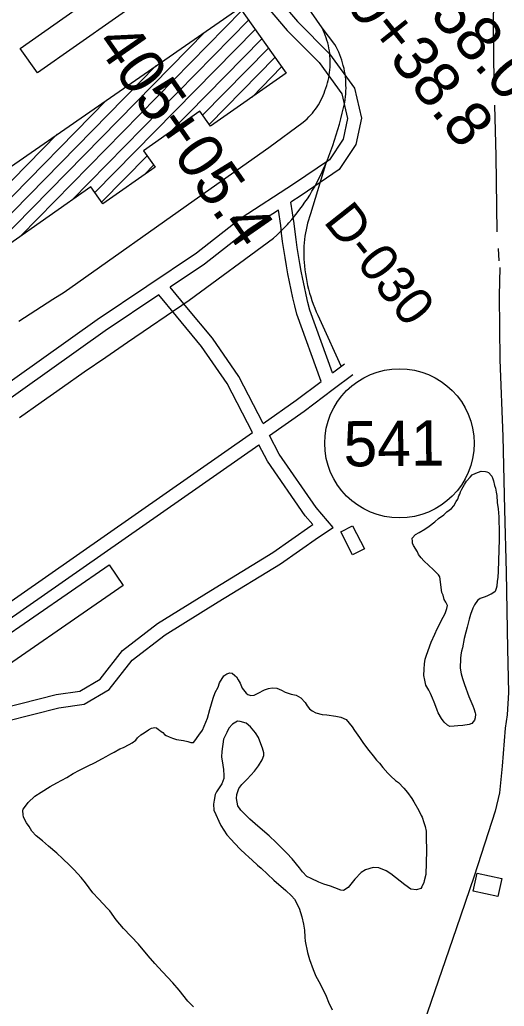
# Model space of a CAD drawing. Extents: x 3625074 to 3663148, y 511451 to 537151.
# Drawn here: x 3645512 to 3646582, y 518337 to 520518 of the extents above; entities that cross this region are included whole.
import ezdxf

# ---------------------------------------------------------------- set-up
doc = ezdxf.new("R2010")
doc.units = 0
for name, color, linetype in [('V-BLDG-OTLN', 7, 'Continuous'), ('V-RAIL-TRAK', 7, 'Continuous'), ('V-RIVR-RANG-IDEN', 7, 'Continuous'), ('V-ROAD-CNTR', 7, 'Continuous'), ('V-ROAD-IDEN', 7, 'Continuous'), ('V-SITE-VEGE', 7, 'Continuous'), ('V-SURV-IDEN', 7, 'Continuous'), ('V-TOPO-SHOR', 7, 'Continuous')]:
    doc.layers.add(name, color=color, linetype=linetype)

msp = doc.modelspace()

# ---------------------------------------------------------------- linework, layer by layer
at = {"layer": 'V-BLDG-OTLN'}
for p, q in [((3645513.8, 520040), (3646002.1, 520538.2)), ((3645626.7, 520119.5), (3646016.7, 520517.4)), ((3645400.9, 519960.6), (3645921.3, 520491.5)), ((3645677.7, 520135.8), (3646031.4, 520496.7)), ((3645843.4, 520269.1), (3646046.1, 520475.9)), ((3645915.5, 520307), (3646060.8, 520455.2)), ((3645091.6, 519680.7), (3645812.2, 520415.9)), ((3645930.1, 520286.2), (3646075.4, 520434.5)), ((3646024.8, 520347.1), (3646090.1, 520413.7)), ((3645077, 519701.5), (3645703.1, 520340.3)), ((3645033.4, 519692.7), (3645594.1, 520264.7)), ((3645692.4, 520115), (3645792.8, 520217.5)), ((3645787.2, 520176.1), (3645807.4, 520196.7))]:
    msp.add_line(p, q, dxfattribs=at)
for points in [[(3645512.3, 520454.8), (3645857.3, 520697.7), (3645895.5, 520643.3), (3645550.5, 520400.5)], [(3643978.6, 519134.6), (3644983.5, 519841.7), (3645997.7, 520544.4), (3646099.9, 520399.9), (3645932.9, 520282.4), (3645909.4, 520315.6), (3645785.3, 520228.2), (3645810.4, 520192.4), (3645695, 520111.2), (3645668.5, 520148.9), (3645299.4, 519889.1), (3645306.3, 519879.2), (3645243.5, 519834.9), (3645274.7, 519790.6), (3645100.6, 519668.1), (3645066.7, 519716.2), (3644966.6, 519645.7), (3645085.1, 519477.3), (3644183.9, 518842.9)], [(3646246.6, 519399.4), (3646272.9, 519348.2), (3646247, 519334.9), (3646220.7, 519386.1)], [(3645740.3, 519267.2), (3645407.2, 519037.4), (3645375.8, 519082.9), (3645708.9, 519312.7)], [(3646513.1, 518591.9), (3646522.2, 518631.7), (3646576.7, 518619.3), (3646567.6, 518579.5)]]:
    msp.add_lwpolyline(points, close=True, dxfattribs=at)
at = {"layer": 'V-RAIL-TRAK'}
for points in [[(3645610.1, 519915.8), (3645909.1, 520128.2), (3646061.7, 520235.3), (3646137.6, 520291.6), (3646142, 520295.3), (3646146.2, 520299.1), (3646150.3, 520303.2), (3646154.2, 520307.3), (3646158, 520311.6), (3646161.6, 520316), (3646165, 520320.6), (3646168.3, 520325.3), (3646171.4, 520330.1), (3646174.3, 520335.1), (3646177, 520340.1), (3646179.5, 520345.2), (3646181.8, 520350.5), (3646184, 520355.8), (3646185.9, 520361.2), (3646187.9, 520366.8), (3646189.8, 520372.5), (3646191.4, 520378.2), (3646192.9, 520384), (3646194.2, 520389.8), (3646195.2, 520395.7), (3646196.1, 520401.6), (3646196.7, 520407.6), (3646197.2, 520413.5), (3646197.4, 520419.5), (3646197.4, 520425.5), (3646197.3, 520431.4), (3646196.9, 520437.4), (3646196.3, 520443.4), (3646195.5, 520449.3), (3646194.5, 520455.2), (3646193.3, 520461), (3646191.9, 520466.8), (3646190.3, 520472.6), (3646188.5, 520478.3), (3646186.6, 520483.9), (3646184.4, 520489.5), (3646182, 520495), (3646179.5, 520500.4), (3646109.2, 520602.8)], [(3645749.6, 519805.2), (3645885.5, 519898), (3646072.3, 520035), (3646079.4, 520041.5), (3646086.3, 520048.2), (3646093, 520055), (3646099.7, 520062), (3646102.9, 520065.5), (3646106.1, 520069.1), (3646112.5, 520076.4), (3646118.6, 520083.7), (3646124.6, 520091.2), (3646130.5, 520098.9), (3646136.2, 520106.6), (3646141.7, 520114.5), (3646147, 520122.4), (3646152.2, 520130.5), (3646157.2, 520138.7), (3646162.6, 520148.1), (3646167.7, 520157.6), (3646172.6, 520167.2), (3646177.4, 520176.8), (3646181.9, 520186.6), (3646186.2, 520196.5), (3646190.4, 520206.4), (3646194.3, 520216.5), (3646198.7, 520228.1), (3646202.9, 520239.8), (3646206.9, 520251.5), (3646210.8, 520263.3), (3646214.4, 520275.2), (3646217.8, 520287.1), (3646221, 520299.1), (3646224, 520311.2), (3646226.8, 520323.3), (3646229.4, 520335.4), (3646230.4, 520341.7), (3646231.2, 520347.9), (3646231.8, 520354.2), (3646232.2, 520360.5), (3646232.4, 520366.8), (3646232.3, 520373.1), (3646232.1, 520379.4), (3646231.7, 520385.7), (3646231, 520391.9), (3646230.2, 520398.2), (3646229.1, 520404.4), (3646227.9, 520410.6), (3646226.4, 520416.7), (3646224.8, 520422.8), (3646222.9, 520428.8), (3646220.9, 520434.8), (3646218.6, 520440.7), (3646216.2, 520446.5), (3646213.6, 520452.2), (3646210.8, 520457.9), (3646207.8, 520463.4), (3646179.5, 520500.4)], [(3646187, 520198.3), (3646153.8, 520089.1), (3646151.5, 520082.2), (3646149.3, 520075.2), (3646147.4, 520068.2), (3646145.6, 520061.1), (3646144.1, 520053.9), (3646142.7, 520046.7), (3646141.6, 520039.5), (3646140.6, 520032.3), (3646139.9, 520025), (3646139.4, 520017.7), (3646139, 520010.5), (3646138.9, 520003.1), (3646139, 519995.8), (3646139.3, 519988.6), (3646139.8, 519981.3), (3646140.4, 519974), (3646141.4, 519965.3), (3646142.6, 519956.6), (3646144, 519948), (3646145.6, 519939.4), (3646147.5, 519930.8), (3646149.5, 519922.3), (3646151.8, 519913.8), (3646154.3, 519905.5), (3646157, 519897.1), (3646159.9, 519888.9), (3646163.1, 519880.7), (3646166.4, 519872.6), (3646170, 519864.6), (3646173.7, 519856.7), (3646177.7, 519848.9), (3646221, 519753)], [(3645509.6, 519851.6), (3645534.6, 519867.9), (3645559.7, 519884), (3645584.9, 519900), (3645610.1, 519915.8)], [(3645511.4, 519639), (3645558.8, 519672.6), (3645606.3, 519706), (3645654, 519739.3), (3645701.7, 519772.3), (3645749.6, 519805.2)]]:
    msp.add_lwpolyline(points, dxfattribs=at)
at = {"layer": 'V-ROAD-CNTR'}
for points in [[(3645874, 520975.9), (3645873.3, 520923), (3645868.2, 520874.8), (3645872.4, 520828.5), (3645909.6, 520766.6), (3646007.1, 520652.7), (3646124.9, 520514.2), (3646195.5, 520442.7), (3646251.3, 520366.7), (3646266.2, 520300.3), (3646254.2, 520242), (3646217.2, 520186.7), (3646133.3, 520129.5), (3646110.5, 520114.8)], [(3645842.4, 520826.9), (3645843.1, 520818.9), (3645885.2, 520748.9), (3645984.3, 520633.2), (3646102.7, 520493.9), (3646172.7, 520423.2), (3646223.4, 520354), (3646235.5, 520300), (3646226, 520253.8), (3646195.5, 520208.2), (3646116.7, 520154.5), (3646000.6, 520079.5), (3645902.1, 520001.7), (3645682.9, 519854.8), (3645377.4, 519637.4), (3644972.2, 519346.6), (3644537.2, 519051), (3644252.9, 518839.5), (3644101.4, 518739.4)], [(3646202.5, 519737.4), (3646152.5, 519876.1), (3646148.3, 519892.6), (3646144.3, 519909.9), (3646140.4, 519927.2), (3646136.8, 519944.5), (3646133.4, 519961.9), (3646130.2, 519979.4), (3646127.3, 519996.9), (3646124.6, 520014.4), (3646122.1, 520032), (3646119.8, 520049.5), (3646117.7, 520067.5), (3646110.5, 520114.8)], [(3646082.9, 520096.9), (3646018.1, 520055.1), (3645919.8, 519977.5), (3645844, 519926.7)], [(3646177.4, 519718.6), (3646123.7, 519867.3), (3646119.2, 519885.5), (3646115, 519903.2), (3646111.1, 519920.9), (3646107.4, 519938.6), (3646103.9, 519956.4), (3646100.7, 519974.2), (3646097.7, 519992.1), (3646094.9, 520010), (3646092.3, 520027.9), (3646090, 520045.9), (3646088, 520063.5), (3646082.9, 520096.9)], [(3646049.4, 519625.6), (3645995.5, 519729.5), (3645937.2, 519813.8), (3645880.7, 519882), (3645844, 519926.7)], [(3645819, 519909.9), (3645700, 519830.1), (3645394.9, 519613), (3644989.4, 519322), (3644554.6, 519026.5), (3644270.2, 518815), (3644116.1, 518713.2)], [(3646026.1, 519605.5), (3645969.8, 519714), (3645913.3, 519795.6), (3645857.6, 519862.9), (3645819, 519909.9)], [(3646202.5, 519737.4), (3646229.3, 519757.5)], [(3646049.4, 519625.6), (3646122.1, 519677.2), (3646177.4, 519718.6)], [(3646063.4, 519598.7), (3646139.8, 519652.9), (3646204.2, 519701.2), (3646247.3, 519733.5)], [(3644116.1, 518713.2), (3644124.9, 518697.5), (3644181.8, 518583.5), (3644266.4, 518486.3), (3644335, 518407.2), (3644330, 518410.6), (3644530.1, 518556.3), (3644967.6, 518852.4), (3645377, 519152.7), (3646026.1, 519605.5)], [(3645192.9, 518980.5), (3645266.9, 518915.3), (3645319.7, 518914.4), (3645481.8, 518967.2), (3645598.3, 518996.7), (3645654.2, 519005.1), (3645709.2, 519037.6), (3645760.2, 519102), (3645832.8, 519158.5), (3645949.7, 519230.9), (3646087.3, 519315.4), (3646171.3, 519374.4), (3646204, 519395.6), (3646166.1, 519440), (3646084.6, 519557.7), (3646063.4, 519598.7)], [(3645217.7, 518998.6), (3645394.4, 519128.3), (3646040, 519578.6)], [(3645217.7, 518998.6), (3645278.4, 518945.1), (3645315.2, 518944.4), (3645473.5, 518996.1), (3645592.4, 519026.2), (3645644, 519033.9), (3645689.2, 519060.6), (3645738.9, 519123.5), (3645815.6, 519183.1), (3645933.9, 519256.5), (3646070.8, 519340.5), (3646154.5, 519399.3), (3646158.9, 519402.2), (3646142.3, 519421.6), (3646058.9, 519542.2), (3646040, 519578.6)]]:
    msp.add_lwpolyline(points, dxfattribs=at)
at = {"layer": 'V-ROAD-IDEN'}
msp.add_circle((3646350.4, 519581.6), 165, dxfattribs=at)
msp.add_circle((3646350.4, 519581.6), 165, dxfattribs=at)
at = {"layer": 'V-SITE-VEGE'}
for points in [[(3646419.1, 519028.6), (3646415.2, 519035.7), (3646408.6, 519047), (3646406.5, 519058.2), (3646404.5, 519068.2), (3646404.9, 519082.2), (3646405.8, 519094.4), (3646407.3, 519104.3), (3646409.9, 519113.5), (3646420.6, 519141.8), (3646428.7, 519159.7), (3646433.7, 519171.8), (3646446.7, 519197.1), (3646451, 519205.2), (3646454.8, 519216.7), (3646456.2, 519223.1), (3646452.9, 519230.2), (3646449.5, 519236.2), (3646446.9, 519246.2), (3646445.2, 519249.1), (3646444.1, 519252.1), (3646439.3, 519286.6), (3646436.5, 519290.8), (3646425.2, 519302.8), (3646415.5, 519311.3), (3646404.1, 519322.1), (3646398.4, 519328.1), (3646392.8, 519335.8), (3646390.1, 519341.7), (3646381.1, 519356), (3646379.5, 519360.7), (3646379, 519364.8), (3646378.7, 519371.8), (3646385.9, 519379.8), (3646393.6, 519384.3), (3646406.7, 519392.1), (3646416.2, 519398.8), (3646428.7, 519408.4), (3646436.5, 519415.7), (3646448.4, 519423.6), (3646455, 519429.8), (3646465.2, 519437.7), (3646470.6, 519443.4), (3646475.5, 519453.1), (3646479.2, 519458.3), (3646481.7, 519465.2), (3646483.6, 519469.3), (3646485.5, 519474.5), (3646488, 519480.2), (3646494.1, 519490.6), (3646498.4, 519498), (3646506.8, 519506.5), (3646511.1, 519511.7), (3646519.3, 519515.5), (3646531.1, 519519.9), (3646540.5, 519519.6), (3646543.4, 519518.9), (3646546.8, 519517.1), (3646554.7, 519508.7), (3646556.9, 519502.8), (3646558.5, 519498.7), (3646560.6, 519488.7), (3646562.2, 519482.8), (3646563.7, 519474), (3646565.2, 519466.4), (3646566.5, 519450.6), (3646568.5, 519437.1), (3646569.7, 519419), (3646570, 519408.4), (3646570.7, 519393.2), (3646570.4, 519380.4), (3646570.6, 519369.3), (3646568.6, 519299.3), (3646567.7, 519285.3), (3646566.3, 519276.6), (3646565.4, 519265.6), (3646564.1, 519260.9), (3646561.5, 519254), (3646559.1, 519251.7), (3646553.2, 519247.8), (3646550.8, 519247.3), (3646543.1, 519244), (3646537.2, 519241.8), (3646529, 519238.6), (3646523, 519234.1), (3646516.3, 519224.3), (3646512.6, 519216.9), (3646507.5, 519203), (3646504.3, 519192.6), (3646499.7, 519175.2), (3646497.1, 519164.2), (3646493.2, 519150.3), (3646489.7, 519129.4), (3646487.7, 519121.8), (3646485.7, 519113.7), (3646484.9, 519105.6), (3646484.3, 519084.6), (3646486.9, 519071.7), (3646489.5, 519061.7), (3646493.8, 519048.7), (3646503.6, 519021.6)], [(3645530.3, 518787.7), (3645545.3, 518801.3), (3645558.9, 518810.2), (3645579.1, 518823.1), (3645593.4, 518830.8), (3645615.3, 518843.1), (3645629.6, 518852), (3645643.8, 518859.2), (3645662.7, 518868.6), (3645676.4, 518875.2), (3645694.1, 518884.6), (3645702.5, 518889.6), (3645713.1, 518895.2), (3645720.2, 518899), (3645732.7, 518906.3), (3645740.9, 518909), (3645753.4, 518915.6), (3645759.9, 518919.5), (3645767.7, 518925.7), (3645771.9, 518930.3), (3645779.1, 518937.1), (3645786.2, 518941.5), (3645795.8, 518948.3), (3645802.3, 518952.2), (3645809.9, 518953.1), (3645814, 518952.4), (3645818, 518948.8), (3645820.3, 518947.6), (3645824.3, 518944.5), (3645827.7, 518942.1), (3645831.7, 518937.9), (3645835.1, 518935.5), (3645841.4, 518932.4), (3645848.9, 518929.8), (3645857.6, 518927.2), (3645873.3, 518924.5), (3645883.2, 518922.4), (3645889.5, 518920.5), (3645895.4, 518920.3), (3645898.4, 518923.8), (3645907.5, 518936.3), (3645915.4, 518947.8), (3645926.1, 518973.8), (3645931.3, 518993.5), (3645939, 519018.3), (3645943.4, 519030.5), (3645949.6, 519042.5), (3645952.8, 519052.4), (3645962.6, 519067.3), (3645969.1, 519071.8), (3645975.6, 519073.9), (3645980.8, 519073.2), (3645987.1, 519068.3), (3645990.5, 519065.3), (3645994.4, 519058.8), (3645998.3, 519051.1), (3646003.3, 519040.4), (3646011.7, 519029.1), (3646015.7, 519026.1), (3646022.1, 519024.1), (3646029.1, 519024.5), (3646038, 519029.5), (3646052.2, 519036.7), (3646061, 519039.4), (3646069.2, 519040.9), (3646079.7, 519040), (3646089.5, 519035.7), (3646097.6, 519031.3), (3646111.5, 519027.4), (3646122.5, 519024.8), (3646132.2, 519019.3), (3646142.4, 519008.5), (3646146.3, 519001.4), (3646152, 518994.8), (3646157.7, 518990.5), (3646165.7, 518985.6), (3646179.6, 518982.3), (3646190.1, 518981.4), (3646209.9, 518978.5)], [(3646503.6, 519021.6), (3646512.3, 519001.5), (3646514.5, 518995.6), (3646517.7, 518985.6), (3646518.2, 518983.2), (3646518, 518975), (3646516.1, 518969.3), (3646510.6, 518962.4), (3646504.7, 518960.2), (3646490.7, 518957.7), (3646479, 518956.9), (3646471.4, 518956.5), (3646461.4, 518955.6), (3646456.8, 518958.7), (3646448.8, 518965.3), (3646443.2, 518973.1), (3646436, 518985.5), (3646433.8, 518992), (3646430.6, 518999.7), (3646426.8, 519009.7), (3646423.5, 519018), (3646419.1, 519028.6)], [(3646209.9, 518978.5), (3646220.9, 518976.5), (3646232.4, 518970.9), (3646246, 518954.7), (3646251, 518946.4), (3646262.3, 518931.5), (3646269.5, 518920.2), (3646277.4, 518909.5), (3646283, 518902.9), (3646292.6, 518890.4), (3646299.9, 518881.4), (3646306.2, 518874.2), (3646313.5, 518864.7), (3646324.8, 518852.1), (3646331, 518846.1), (3646341.3, 518835.9), (3646348.1, 518831.6), (3646360, 518819), (3646368, 518809.4), (3646377.5, 518796.3), (3646382, 518789.2), (3646393.1, 518770.2), (3646398.6, 518759), (3646400.8, 518754.8), (3646404.6, 518743.6), (3646407.3, 518734.2), (3646409.3, 518724.2), (3646409.1, 518718.4), (3646409.4, 518708.4), (3646409.3, 518702), (3646410.1, 518689.7), (3646410.4, 518681), (3646408.9, 518628.5), (3646405, 518614.6), (3646404.3, 518610.5), (3646400, 518601.3), (3646397.5, 518597.3), (3646388.1, 518594.6), (3646375.3, 518596.2), (3646362.2, 518605.9), (3646331.3, 518630.1), (3646321, 518636.8), (3646304.9, 518643.1), (3646292, 518644.1), (3646275.5, 518638.7), (3646265.5, 518633.1), (3646251.6, 518617.8), (3646237.1, 518599.5), (3646227, 518593.4), (3646220.6, 518593.6), (3646207.3, 518598.6), (3646198, 518602.4), (3646183, 518606.9), (3646172.6, 518611.3), (3646155.3, 518619.3), (3646146.1, 518624.3), (3646135.9, 518634.5), (3646129.7, 518642.8), (3646113.4, 518663.1), (3646101.5, 518675.7), (3646095.8, 518681.2), (3646078.2, 518699.2), (3646062.9, 518713.6), (3646037.2, 518735.4), (3646020.1, 518751), (3645999.7, 518770.3), (3645993, 518780.4), (3645990.5, 518796.2), (3645990.8, 518805.6), (3645995.8, 518818.3), (3646001.9, 518827.4), (3646013.9, 518839.3), (3646030.2, 518857), (3646039.2, 518868.4), (3646047.2, 518882.2), (3646051, 518891.4), (3646051.1, 518897.2), (3646047.9, 518907.8), (3646044.1, 518917.3), (3646038.7, 518931.4), (3646032.6, 518941.5), (3646021.3, 518954.7), (3646011.6, 518962.6), (3645998.3, 518967), (3645992.4, 518967.2), (3645985.3, 518963.3), (3645981.7, 518961.1), (3645973.3, 518952), (3645969, 518942.2), (3645961.5, 518927.8), (3645957.8, 518900.5), (3645957.5, 518888.8), (3645959.9, 518870.1), (3645961.4, 518860.7), (3645962.8, 518847.2), (3645962.6, 518840.8), (3645960.6, 518834.4), (3645958.2, 518829.2), (3645953.9, 518822.4), (3645946, 518810.9), (3645943.5, 518805.1)], [(3645943.5, 518805.1), (3645940.8, 518793), (3645939.4, 518783.7), (3645940.7, 518770.8), (3645944.5, 518760.8), (3645951.1, 518746.6), (3645955.5, 518736.5), (3645969, 518716.3), (3645978.6, 518706.1), (3645985.9, 518697.7), (3645999.6, 518683.9), (3646009.2, 518674.3), (3646017.8, 518667), (3646025.1, 518659.8), (3646036.5, 518649), (3646045.1, 518642.3), (3646072.9, 518615.8), (3646099.1, 518592.9), (3646112.2, 518580.9), (3646118.4, 518573.7), (3646129, 518554.1), (3646134.8, 518534.7), (3646138.5, 518518.8), (3646140.4, 518505.4), (3646141.2, 518490.2), (3646142.1, 518480.8), (3646147.2, 518456.1), (3646152, 518440.8), (3646159.6, 518418.4), (3646165.6, 518403.7), (3646175, 518386.5), (3646188.2, 518359.8), (3646193.7, 518346.2), (3646201.4, 518329.1)], [(3645895.1, 518335.5), (3645883.2, 518348.6), (3645864.1, 518372.5), (3645849.9, 518388.7), (3645827.3, 518413.3), (3645809.7, 518431.9), (3645795, 518448.6), (3645773.6, 518474.3), (3645740.7, 518509.1), (3645724.3, 518528.3), (3645710.3, 518547.9), (3645709.4, 518549.8), (3645705.2, 518553.3), (3645685.3, 518574.9), (3645672.9, 518588.1), (3645657.2, 518610.1), (3645647, 518622.1), (3645631.7, 518638.9), (3645622.1, 518648.5), (3645606.1, 518663.5), (3645593.6, 518675.6), (3645575.4, 518690.7), (3645561.7, 518702.7), (3645548, 518714.2), (3645538.4, 518724.4), (3645532.3, 518734.5), (3645526.7, 518742.8), (3645520, 518755.3), (3645519, 518761.2), (3645518.1, 518768.8), (3645519.4, 518772.8), (3645524.2, 518779.7), (3645530.3, 518787.7)]]:
    msp.add_lwpolyline(points, dxfattribs=at)
at = {"layer": 'V-TOPO-SHOR'}
msp.add_line((3646568.4, 520012.2), (3646569.6, 519985), dxfattribs=at)
for points in [[(3646315.1, 521182.8), (3646354, 521144.6), (3646375, 521120.8), (3646406.9, 521080.2), (3646438, 521033.4), (3646467.6, 520982.3), (3646491.7, 520934), (3646513.5, 520873.6), (3646533.6, 520812), (3646542.9, 520772.6), (3646549.1, 520732.8), (3646553.3, 520680.6), (3646559.1, 520621.4), (3646557.4, 520503.7), (3646559.2, 520379)], [(3646560.6, 520329.1), (3646563.6, 520216.5), (3646565.4, 520048.9)], [(3646572.4, 519970), (3646571, 519907.9), (3646572.1, 519766.1), (3646578.9, 519596.4), (3646582.3, 519435.5), (3646586.1, 519296.8), (3646588.7, 519127.4), (3646591.2, 519030.6), (3646588, 518981.4), (3646583.8, 518952.2), (3646577.2, 518868.2), (3646571.1, 518809.1), (3646561.9, 518768.5), (3646515.2, 518624.9), (3646475.5, 518508)], [(3646475.5, 518508), (3646412.3, 518323.9), (3646365, 518184.8)]]:
    msp.add_lwpolyline(points, dxfattribs=at)

# ---------------------------------------------------------------- texts
at = {"layer": 'V-RIVR-RANG-IDEN'}
msp.add_text('D-030', height=83, rotation=308.4343, dxfattribs=at).set_placement((3646180.8, 520071.5))
at = {"layer": 'V-ROAD-IDEN'}
msp.add_text('541', height=100, rotation=0.575, dxfattribs=at).set_placement((3646227.3, 519530.4))
at = {"layer": 'V-SURV-IDEN'}
for s, rotation, p in [('411+70.8', 312.242, (3646346.1, 520812.6)), ('410+58.0', 311.2412, (3646216.2, 520754.1)), ('409+38.8', 308.5875, (3646137.4, 520667.1)), ('405+05.4', 304.8689, (3645676.5, 520466.3))]:
    msp.add_text(s, height=100, rotation=rotation, dxfattribs=at).set_placement(p)

doc.saveas('drawing.dxf')
